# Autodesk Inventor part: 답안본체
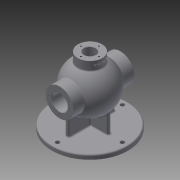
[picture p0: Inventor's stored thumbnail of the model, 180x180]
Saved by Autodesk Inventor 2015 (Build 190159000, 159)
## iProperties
Created: 2020-08
Part Number: 답안본체
Material: 일반
Document SubType Name: Modeling
Designer: now
Density: 1 g/cm^3
Appearance: 기본값
Author: now
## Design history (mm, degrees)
sketch "스케치1"
  geometry: C1 r 85 at (0, 0); 1 further point
  constraints: 1 centre point, 1 coincident
  dimensions: "d0" = 170 diameter of C1
extrude "돌출1" new body sketch "스케치1" distance "d1" = 10; taper "d2" = 0 deg
fillet "모깎기1" dims "d3" = 3
sketch "스케치2"
  geometry: L1 (-43, -4)-(43, -4); L2 (43, -4)-(43, 4); L3 (43, 4)-(-43, 4); L4 (-43, 4)-(-43, -4); L5 (-43, -4)-(43, 4); L6 (43, -4)-(-43, 4); L7 (-4, -52)-(4, -52); L8 (4, -52)-(4, 52); L9 (4, 52)-(-4, 52); L10 (-4, 52)-(-4, -52); L11 (-4, -52)-(4, 52); L12 (4, -52)-(-4, 52); C1 r 82 at (0, 0) reference
  constraints: 24 end point, 4 midpoint, 4 parallel, 2 horizontal, 2 perpendicular
  dimensions: "d42" = 8 distance between parallel lines of L8 L10; "d43" = 8 distance between parallel lines of L3 L1; "d44" = 86 distance of L1.start L1.end; "d45" = 104 distance of L7.end L8.end
extrude "돌출2" join sketch "스케치2" distance "d8" = 75; taper "d9" = 0 deg
node "작업 평면1"
fillet "모깎기2" dims "d46" = 3
sketch "스케치7"
  geometry: L1 (-82, 10)-(-52, 10) reference; L2 (-52, 10)-(-52, 85) reference; L3 (-52, 85)-(52, 85) reference; L4 (52, 85)-(52, 10) reference; L5 (52, 10)-(82, 10) reference; L6 (85, 7)-(85, 0) reference; L7 (85, 0)-(-85, 0) reference; L8 (-85, 0)-(-85, 7) reference; L9 (-53, 85)-(53, 85); L10 (4, 85)-(4, 10) reference; A1 r 3 centre (-82, 7) between (-82, 10) and (-85, 7) reference; A2 r 3 centre (82, 7) between (85, 7) and (82, 10) reference; A3 r 53 centre (0, 85) between (53, 85) and (-53, 85); 2 further points
  constraints: 2 end point, 2 midpoint, 2 point on circle, 1 centre point, 1 coincident, 1 horizontal
  dimensions: "d49" = 53 radius of A3
revolve "회전3" sketch "스케치7" stored, may be unused: angle "d50" = 90 deg
sketch "스케치4"
  geometry: C1 r 27 at (0, 0); 1 further point
  constraints: 1 centre point, 1 coincident
  dimensions: "d14" = 54 diameter of C1
extrude "돌출3" join sketch "스케치4" stored distance "d15" = 65; taper "d16" = 0 deg
sketch "스케치5"
  geometry: L1 (-82, 10)-(-43, 10) reference; L2 (-27, 130.607)-(-27, 150) reference; L3 (-27, 150)-(27, 150) reference; L4 (27, 150)-(27, 130.607) reference; L5 (43, 10)-(82, 10) reference; L6 (85, 7)-(85, 0) reference; L7 (85, 0)-(-85, 0) reference; L8 (-85, 0)-(-85, 7) reference; L9 (-43, 10)-(-43, 54.016) reference; L10 (43, 54.016)-(43, 10) reference; C1 r 31 at (0, 85); A1 r 3 centre (-82, 7) between (-82, 10) and (-85, 7) reference; A2 r 3 centre (82, 7) between (85, 7) and (82, 10) reference; A3 r 53 centre (0, 85) between (-27, 130.607) and (-53, 85) reference; A4 r 53 centre (0, 85) between (-53, 85) and (-43, 54.016) reference; A5 r 53 centre (0, 85) between (43, 54.016) and (53, 85) reference; A6 r 53 centre (0, 85) between (53, 85) and (27, 130.607) reference; 2 further points
  constraints: 1 centre point, 1 coincident
  dimensions: "d17" = 62 diameter of C1
extrude "돌출4" join sketch "스케치5" stored distance "d18" = 136; taper "d19" = 0 deg
sketch "스케치6"
  geometry: L1 (-82, 10)-(-52, 10) reference; L2 (-52, 54)-(-68, 54) reference; L3 (-68, 54)-(-68, 116) reference; L4 (-68, 116)-(-42.988, 116) reference; L5 (-27, 130.607)-(-27, 150) reference; L6 (-27, 150)-(27, 150) reference; L7 (27, 150)-(27, 130.607) reference; L8 (42.988, 116)-(68, 116) reference; L9 (68, 116)-(68, 54) reference; L10 (68, 54)-(52, 54) reference; L11 (52, 10)-(82, 10) reference; L12 (85, 7)-(85, 0) reference; L13 (85, 0)-(-85, 0) reference; L14 (-85, 0)-(-85, 7) reference; L15 (-43, 85)-(43, 85); L16 (-52, 10)-(-52, 54) reference; L17 (52, 54)-(52, 10) reference; A1 r 3 centre (-82, 7) between (-82, 10) and (-85, 7) reference; A2 r 3 centre (82, 7) between (85, 7) and (82, 10) reference; A3 r 43 centre (0, 85) between (43, 85) and (-43, 85); A4 r 53 centre (0, 85) between (-27, 130.607) and (-42.988, 116) reference; A5 r 53 centre (0, 85) between (42.988, 116) and (27, 130.607) reference; 4 further points
  constraints: 2 coincident, 2 end point, 2 point on circle, 1 centre point, 1 horizontal, 1 midpoint
  dimensions: "d20" = 86 diameter of A3
revolve "회전2" sketch "스케치6" stored, may be unused: angle "d21" = 90 deg
hole "구멍1" diameter "d24" = 35; stored, may be unused: countersink angle "d28" = 90 deg, drill point angle "d30" = 118 deg; dims "d22" = 10, "d23" = 10, "d25" = 6, "d26" = 4, "d27" = 2, "d29" = 8
hole "구멍2" diameter "d33" = 26; stored, may be unused: countersink angle "d37" = 90 deg, drill point angle "d39" = 118 deg; dims "d34" = 6, "d35" = 4, "d36" = 2, "d38" = 8, "d40" = 10, "d41" = 10
sketch "스케치8"
  geometry: C1 r 17.5 at (0, 0) reference; 2 further points
  constraints: 1 vertical alignment
  dimensions: "d51" = 24 distance of C1.centre point (0, 24)
hole "구멍3" sketch "스케치8" at (0, 24) diameter "d52" = 3.242; stored, may be unused: countersink angle "d56" = 90 deg, drill point angle "d58" = 118 deg; dims "d53" = 12, "d54" = 4, "d55" = 2, "d57" = 15
sketch "스케치9"
  geometry: C1 r 13 at (0, 0) reference; 1 further point
  constraints: 1 horizontal alignment
  dimensions: "d62" = 20 distance of C1.centre point (20, 0)
hole "구멍4" sketch "스케치9" at (20, 0) diameter "d63" = 3.242; stored, may be unused: countersink angle "d67" = 90 deg, drill point angle "d69" = 118 deg; dims "d64" = 12, "d65" = 4, "d66" = 2, "d68" = 15
fillet "모깎기3" dims "d73" = 3
chamfer "모따기1" distance "d74" = 1; stored, may be unused: second distance "d75" = 2, angle "d76" = 45 deg
sketch "스케치10"
  geometry: C1 r 82 at (0, 0) reference; 1 further point
  constraints: 1 horizontal alignment
  dimensions: "d77" = 72.5 distance of point (-72.5, 0) C1.centre
hole "구멍5" sketch "스케치10" at (-72.5, 0) diameter "d78" = 9; stored, may be unused: countersink angle "d82" = 90 deg, drill point angle "d84" = 118 deg; dims "d79" = 12, "d80" = 4, "d81" = 2, "d83" = 15
fillet "모깎기4" dims "d88" = 3
node "작업 평면2"
sketch "스케치11"
  geometry: L1 (27, 150)-(-27, 150) reference; L2 (-27, 132.286)-(27, 132.286) reference; 2 further points
  constraints: 1 other
  dimensions: "d90" = 9 distance from line of L1 point (0, 141); "d91" = 27 horizontal distance of L1.end point (0, 141)
feature "엠보싱1" sketch "스케치11" dims "d2" = 0, "d92" = 0.5, "d93" = 0
node "작업 평면3"
sketch "스케치12"
  geometry: C1 r 17.5 at (0, 0) reference; C2 r 18.5 at (0, 0); 1 further point
  constraints: 1 centre point, 1 coincident
  dimensions: "d95" = 37 diameter of C2
extrude "돌출5" cut sketch "스케치12" distance "d96" = 1.75; taper "d97" = 0 deg
node "솔리드1"
pattern_circular "원형 패턴1" dims angle "d60" = 360 deg
mirror "대칭1"
pattern_circular "원형 패턴2" dims angle "d71" = 360 deg
pattern_circular "원형 패턴3" dims angle "d86" = 360 deg
node "투영된 루프1"
node "절단 모서리 투영2"
node "절단 모서리 투영3"
node "절단 모서리 투영4"
other parameters: "d10" = 106, "d48" = 106, "d89" = 27, "d94" = -16
